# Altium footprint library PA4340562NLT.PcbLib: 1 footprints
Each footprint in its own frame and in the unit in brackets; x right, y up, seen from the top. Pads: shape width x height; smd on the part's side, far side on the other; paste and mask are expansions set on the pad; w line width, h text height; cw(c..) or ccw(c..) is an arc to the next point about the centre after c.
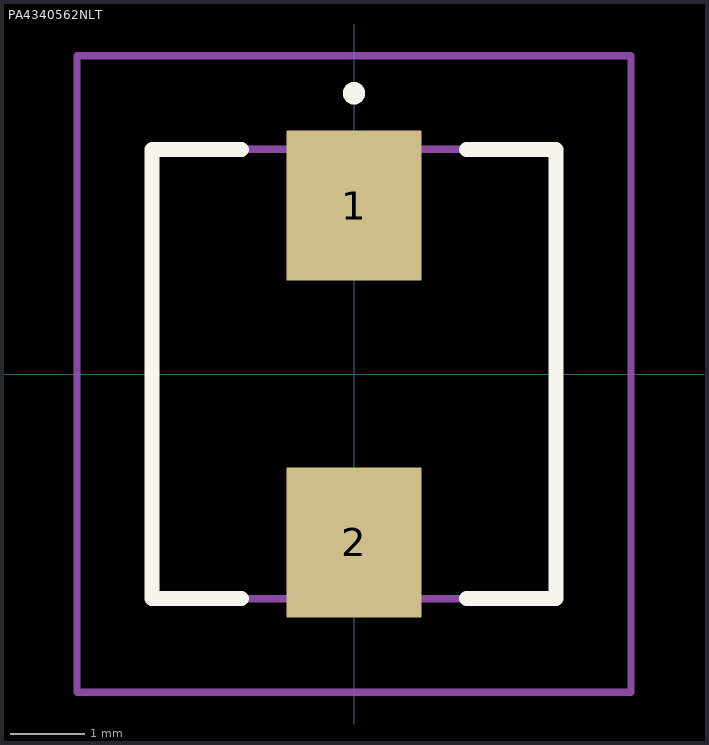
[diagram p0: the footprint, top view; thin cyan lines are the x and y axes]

## PA4340562NLT [mm]
pads (2):
  rect 1.8x2 smd: 1(0,2.25) 2(0,-2.25)
Top Overlay:
  lines w0.2: -1.5,-3 -2.7,-3 -2.7,3 -1.5,3 ; 1.5,-3 2.7,-3 2.7,3 1.5,3 ; 0,3.7 cw(c0,3.75) 0,3.8 ; 0,3.7 0,3.7 ; 0,3.7 ccw(c0,3.75) 0,3.8 ; 0,3.7 cw(c0,3.75) 0,3.8 ; 0,3.8 0,3.8 ; 0,3.8 0,3.8
Mechanical 15:
  lines w0.1: -2.7,-3 2.7,-3 2.7,3 -2.7,3 -2.7,-3
Mechanical 20:
  lines w0.1: -3.7,-4.25 3.7,-4.25 3.7,4.25 -3.7,4.25 -3.7,-4.25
